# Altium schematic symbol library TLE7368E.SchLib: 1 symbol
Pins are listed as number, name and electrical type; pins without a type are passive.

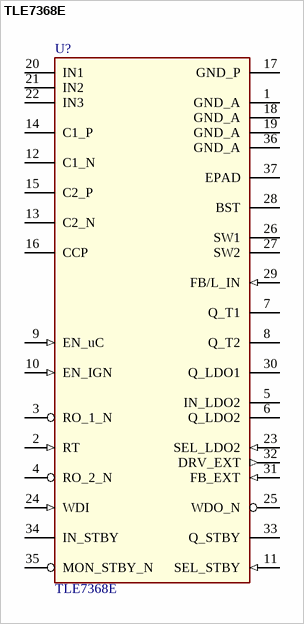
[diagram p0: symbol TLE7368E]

## TLE7368E
designator U?
Next Generation Micro Controller Supply with LDO3 control for an external NPN power stage: 1.2V, ±2%; Manufacturer: Infineon Technologies
pins: 1 GND_A (power) "Analog Ground Connection", 2 RT (in) "Reset and Watchdog Timing Pin", 3 RO_1_N (oc) "Reset Output Q_LDO1", 4 RO_2_N (oc) "Reset Output Q_LDO2 and FB_EXT", 5 IN_LDO2 (power) "LDO2 Input", 6 Q_LDO2 (power) "Voltage Regulator 2 Output", 7 Q_T1 (power) "Tracking Regulator 1 Output", 8 Q_T2 (power) "Tracking Regulator 2 Output", 9 EN_uC (in) "Enable Input Microcontroller", 10 EN_IGN (in) "Enable Input Ignition Line", 11 SEL_STBY (in) "Selection Input for Stand-by Regulator", 12 C1_N "Charge Pump Negative #1", 13 C2_N "Charge Pump Negative #2", 14 C1_P "Charge Pump Positive #1", 15 C2_P "Charge Pump Positive #2", 16 CCP (power) "Charge Pump Output", 17 GND_P (power) "Power Ground", 18 GND_A (power) "Analog Ground Connection", 19 GND_A (power) "Analog Ground Connection", 20 IN1 (power) "Buck Regulator Input", 21 IN2 (power) "Buck Regulator Input", 22 IN3 (power) "Buck Regulator Input", 23 SEL_LDO2 (in) "Selection Input LDO2", 24 WDI (in) "Window Watchdog Input", 25 WDO_N (oc) "Window Watchdog Output", 26 SW1 (power) "Buck Power Stage’s Output", 27 SW2 (power) "Buck Power Stage’s Output", 28 BST (power) "Bootstrap Driver Supply Input", 29 FB/L_IN (in) "Buck Converter Feedback Input Plus Input for LDO1 and Trackers", 30 Q_LDO1 (power) "Voltage Regulator 1 Output", 31 FB_EXT (in) "External Regulator Feedback Input", 32 DRV_EXT (out) "Bipolar Power Stage Driver Output", 33 Q_STBY (power) "Stand-by Regulator Output", 34 IN_STBY (power) "Input to Stand-by Regulator", 35 MON_STBY_N (oc) "Monitoring Output for Stand-by Regulator", 36 GND_A (power) "Analog Ground Connection", 37 EPAD (power) "Exposed Pad"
